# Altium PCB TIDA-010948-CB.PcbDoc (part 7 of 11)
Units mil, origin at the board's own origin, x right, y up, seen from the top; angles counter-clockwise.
Board outline 8100 x 8400 mil, 8 copper layers (L01 - TOP, L02 - GND, L03 - SIG, L04 - GND, L05 - PWR, L06 - SIG, L07 - GND, L08 - BOTTOM), stack 59.656 mil thick; 711 components, 572 nets, 2646 pads, 1325 vias.
Unrouted connection lines stored in the file: 988.
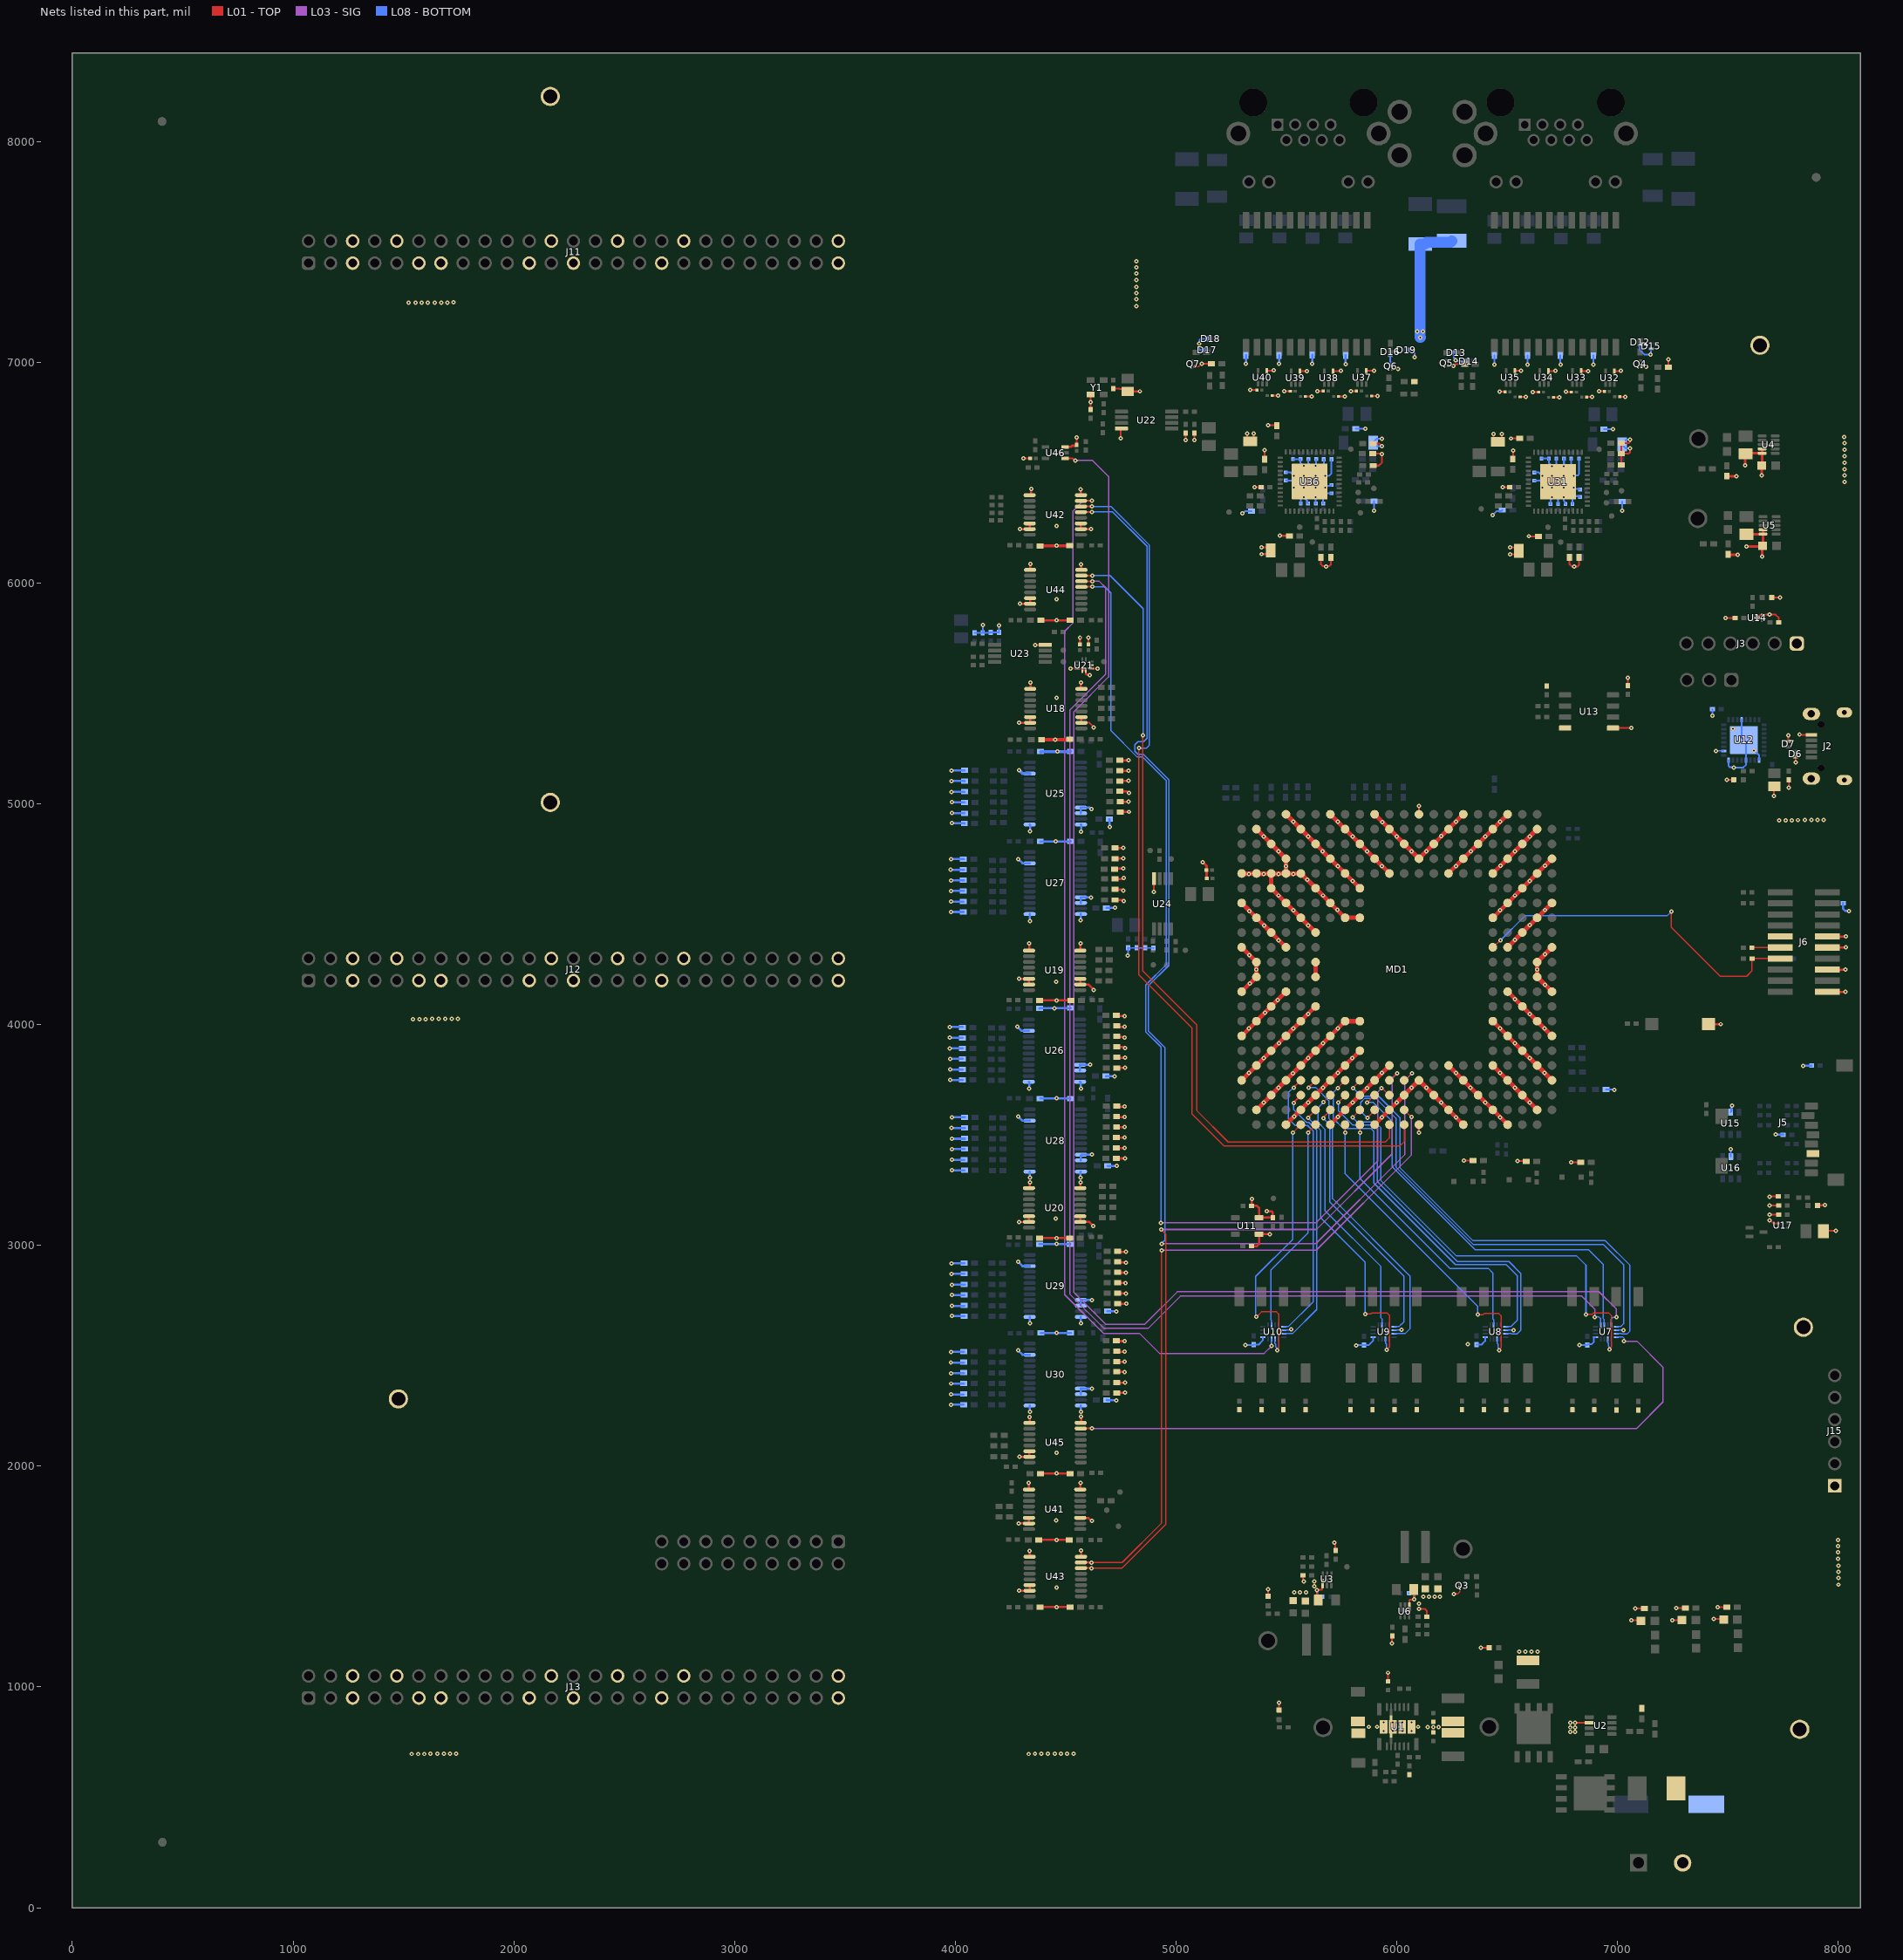
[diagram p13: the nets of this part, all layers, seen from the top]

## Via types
v1: diameter 19.68, hole 7.87, L01 - TOP to L08 - BOTTOM, 1310 vias
v2: diameter 20, hole 7.87, L01 - TOP to L08 - BOTTOM, tented both sides, 7 vias
v3: diameter 200, hole 144, L01 - TOP to L08 - BOTTOM, 6 vias
v4: diameter 20, hole 8, L01 - TOP to L08 - BOTTOM, tented both sides, 2 vias

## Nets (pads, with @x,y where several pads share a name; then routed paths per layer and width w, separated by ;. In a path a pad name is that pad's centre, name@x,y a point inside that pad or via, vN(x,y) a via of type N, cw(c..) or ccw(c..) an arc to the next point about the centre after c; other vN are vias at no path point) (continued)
GND: C1.1 C2.1 C3.2 C4.1 C5.1 C6.2 C7.2 C8.1 C10.1 C12.1 C13.2 C15.2 C17.2 C18.2 C19.2 C20.1 C21.2 C22.2 C24.2 C26.2 C27.2 C28.2 C29.2 C30.2 C31.2 C32.2 C33.2 C35.2 C41.1 C42.1 C43.1 C44.2 C45.2 C46.2 C47.1 C48.2 C49.1 C50.2 C51.1 C52.2 C53.2 C54.2 C55.2 C56.1 C57.2 C58.2 C59.2 C60.2 C61.2 C62.2 C63.2 C64.2 C65.2 C66.2 C67.2 C68.2 C69.2 C70.2 C71.2 C72.2 C73.2 C74.2 C75.2 C76.2 C77.2 C78.2 C79.1 C80.1 C81.2 C82.2 C83.2 C84.2 C85.2 C86.2 C87.2 C88.2 C89.2 C90.2 C91.2 C92.2 C93.1 C94.1 C95.2 C96.2 C97.2 C98.2 C99.2 C100.2 C101.1 C102.2 C103.2 C104.2 C105.2 C106.2 C107.2 C108.1 C109.2 C110.2 C111.2 C112.2 C113.2 C114.2 C115.2 C116.2 C117.2 C118.2 C119.2 C120.2 C121.2 C122.2 C123.2 C124.2 C125.2 C126.2 C127.2 C128.2 C129.2 C130.2 C131.2 C132.2 C133.2 C134.2 C135.2 C136.1 C137.2 C138.2 C139.1 C140.2 C142.1 C143.1 C144.1 C145.1 C146.1 C147.1 C148.1 C149.1 C150.2 C151.2 C152.2 C153.2 C154.2 C155.2 C156.2 C157.2 C158.2 C159.2 C160.2 C161.2 C162.2 C163.2 C164.2 C165.2 C166.2 C167.2 C168.2 C169.2 C170.2 C171.2 C172.2 C173.2 C174.2 C175.2 C176.2 C177.1 C178.1 C179.2 C180.2 C181.1 C182.2 C184.1 C185.1 C186.1 C187.1 C188.1 C189.1 C190.1 C191.1 C193.1 C194.2 C195.1 C196.2 C197.1 C198.2 C199.1 C200.2 C201.1 C202.2 C203.2 C204.2 C205.1 C206.1 D1.1 D2.1 D3.1 D4.1 D11.1 D12.1 D13.1 D14.1 D15.1 D16.1 D17.1 D18.1 D19.1 J1.2 J5.6 J6.10 J6.12 J6.16 J6.20 J11.5 J11.6 J11.10 J11.11 J11.13 J11.21 J11.24 J11.25 J11.30 J11.33 J11.36 J11.49 J11.50 J12.5 J12.6 J12.10 J12.11 J12.13 J12.21 J12.24 J12.25 J12.30 J12.33 J12.36 J12.49 J12.50 J13.5 J13.6 J13.10 J13.11 J13.13 J13.21 J13.24 J13.25 J13.30 J13.33 J13.36 J13.49 J13.50 J15.1 MD1.A4 MD1.A7 MD1.A10 MD1.A13 MD1.A16 MD1.A19 MD1.AA2 MD1.AA5 MD1.AA8 MD1.AA11 MD1.AA15 MD1.AA18 MD1.AA21 MD1.AB4 MD1.AB7 MD1.AB10 MD1.AB13 MD1.AB16 MD1.AB19 MD1.B2 MD1.B5 MD1.B8 MD1.B11 MD1.B15 MD1.B18 MD1.B21 MD1.C3 MD1.C6 MD1.C9 MD1.C12 MD1.C14 MD1.C17 MD1.C20 MD1.D4 MD1.D7 MD1.D10 MD1.D13 MD1.D16 MD1.D19 MD1.D22 MD1.E1 MD1.E2 MD1.E3 MD1.E4 MD1.E5 MD1.E8 MD1.E11 MD1.E15 MD1.E18 MD1.E21 MD1.F3 MD1.F6 MD1.F9 MD1.F20 MD1.G1 MD1.G4 MD1.G7 MD1.G19 MD1.G22 MD1.H2 MD1.H5 MD1.H8 MD1.H9 MD1.H18 MD1.H21 MD1.J3 MD1.J6 MD1.J20 MD1.K1 MD1.K4 MD1.K19 MD1.K22 MD1.L2 MD1.L6 MD1.L21 MD1.M2 MD1.M6 MD1.M21 MD1.N1 MD1.N4 MD1.N19 MD1.N22 MD1.P3 MD1.P6 MD1.P20 MD1.R2 MD1.R5 MD1.R8 MD1.R9 MD1.R18 MD1.R21 MD1.T1 MD1.T4 MD1.T7 MD1.T19 MD1.T22 MD1.U3 MD1.U6 MD1.U9 MD1.U20 MD1.V2 MD1.V5 MD1.V8 MD1.V11 MD1.V15 MD1.V18 MD1.V21 MD1.W1 MD1.W4 MD1.W7 MD1.W10 MD1.W13 MD1.W16 MD1.W19 MD1.W22 MD1.Y3 MD1.Y6 MD1.Y9 MD1.Y12 MD1.Y14 MD1.Y17 MD1.Y20 NT1.2 NT2.2 Q3.2 Q4.2 Q5.2 Q6.2 Q7.2 R4.2 R12.1 R17.1 R18.1 R19.1 R23.1 R25.1 R26.1 R35.1 R36.1 R37.1 R38.1 R39.1 R40.1 R41.1 R42.1 R51.1 R52.1 R53.1 R54.1 R55.1 R56.1 R57.1 R58.1 R60.1 R83.1 R84.1 R89.1 R90.1 R109.2 R131.2 R132.2 R145.2 R146.2 R147.2 R148.2 R149.2 R150.2 R151.2 R152.2 R153.2 R154.2 R155.2 R156.2 R159.2 R160.2 R173.2 R174.2 R175.2 R176.2 R177.2 R178.2 R179.2 R180.2 R181.2 R182.2 R183.2 R184.2 R186.2 R193.2 R194.2 R195.2 R196.2 R197.2 R198.2 R200.2 R207.2 R208.2 R209.2 R210.2 R211.2 R212.2 R221.1 R222.1 R223.1 R224.1 R225.1 R226.1 R227.1 R235.2 R252.1 R261.1 R262.1 R263.1 R264.1 R265.1 R266.1 R267.1 R275.2 R314.1 R315.1 R316.1 S1.1 TP1.1 TP2.1 TP3.1 TP4.1 TP40.1 TP41.1 U1.17 U1.18 U1.19 U1.20 U2.2 U3.4@5664.31,1468.28 U4.9 U4.10 U5.9 U5.10 U6.4@6056.69,1361.72 U7.6 U7.13 U8.6 U8.13 U9.6 U9.13 U10.6 U10.13 U11.1 U11.3 U13.4 U15.2 U16.2 U17.C1 U18.2 U18.3 U18.8 U18.9 U18.14 U18.15 U19.2 U19.3 U19.8 U19.9 U19.14 U19.15 U20.2 U20.3 U20.8 U20.9 U20.14 U20.15 U21.1 U21.2 U21.3 U21.4 U21.10 U22.4 U23.4 U24.4 U25.9 U25.10 U25.12 U25.13 U25.22 U26.9 U26.10 U26.12 U26.13 U26.22 U27.9 U27.10 U27.12 U27.13 U27.22 U28.9 U28.10 U28.12 U28.13 U28.22 U29.9 U29.10 U29.12 U29.13 U29.22 U30.9 U30.10 U30.12 U30.13 U30.22 U31.49 U32.4 U33.4 U34.4 U35.4 U36.49 U37.4 U38.4 U39.4 U40.4 U41.3 U41.8 U41.9 U41.14 U41.15 U42.2 U42.3 U42.8 U42.9 U42.14 U42.15 U43.8 U43.9 U43.14 U43.15 U44.8 U44.9 U44.14 U44.15 U45.8 U45.9 U45.14 U45.15 U46.3 Y1.2 | length 27395.5
  L01 - TOP w6: v1(4521.5,5613) 4521.81,5612.69 4550.84,5612.69 U21.10@4551.15,5612.39 U21.10@4551.21,5612.32 ; Q7.2@5084.89,6980.2 5100.7,6980.2 5103.15,6980.2 5115.44,6992.5 v1(5117.5,6992.5) ; Q6.2@5979.39,6969.7 6004.8,6969.7 v1(6005.5,6969) ; Q5.2@6232.39,6983.7 v1@6260.2,6983.7 ; v1(6259,1421) 6276,1421 6284.2,1429.2 Q3.2@6284.2,1452.95 ; Q4.2@7109.54,6979.85 v1@7130.35,6979.85
  L01 - TOP w8: v1(4289,3106.5) 4289.24,3106.26 4333.62,3106.26 U20.15@4333.86,3106.02 ; v1(4308,6564.5) C203.2@4338.51,6564.5 ; v1(4361.5,5719.5) 4361.69,5719.69 4406.98,5719.69 U23.4@4407.17,5719.89 ; v1@4457.66,6168.5 v1(4459.16,6170) ; v1(4549,6658.5) 4549.25,6658.25 4549.25,6626.24 C204.2@4549.5,6625.99 ; U21.10@4551.21,5612.32 4574.71,5612.32 4574.77,5612.26 U21.1@4574.77,5606.48 U21.1@4574.83,5606.42 ; C55.2@4564.5,5721.99 v1(4564.5,5752.5) ; U18.2@4571.44,5367.02 4607.81,5367.02 4627.5,5347.33 v1(4627.5,5345) ; U21.1@4574.83,5605.5 4590.45,5605.5 4590.52,5605.43 U21.2@4590.52,5604.51 4590.58,5604.45 4590.58,5588.19 4593.03,5585.74 4607.26,5585.74 v1(4609.5,5583.5) ; C56.1@4603,5721.99 v1(4603,5752) ; R109.2@4612,6786.19 4612.25,6786.44 4612.25,6818.25 v1(4612.5,6818.5) 4612.5,6853.55 Y1.2@4612.97,6854.02 Y1.2@4612.57,6854.42 ; U21.4@4614.14,5628.13 U21.3@4614.14,5612.39 4614.2,5612.32 4644.18,5612.32 v1(4645,5611.5) ; C57.2@4715.5,6879.81 4744.15,6879.81 4745.18,6878.78 4769.11,6878.78 C58.2@4780.05,6867.85 ; v1(4749.5,6655.5) 4749.5,6696.79 U22.4@4752.33,6699.61 ; C58.2@4780.08,6867.87 v1(4836.55,6867.87) ; v1(4899.5,4601.5) 4899.56,4601.56 4899.56,4661.12 U24.4@4899.61,4661.17 ; C54.2@5043,6679.31 5043.25,6679.06 5043.25,6648.75 v1(5043.5,6648.5) ; v1(5082.5,6648) 5082.75,6648.25 5082.75,6678.56 C53.2@5083,6678.81 ; v1@5114.34,6992.5 v1(5117.5,6992.5) 5118.25,6993.25 5159.13,6993.25 C178.1@5159.88,6994 ; v1(5321.5,6677) 5321.5,6653.43 5336,6638.93 5352.5,6655.43 v1(5352.5,6677.5) ; v1(5336.5,6874) 5337,6874.5 5366.98,6874.5 C191.1@5367.48,6875 ; v1(5355.5,6434) 5355.75,6433.75 5385.56,6433.75 C180.2@5385.81,6433.5 ; v1(5387.5,6131) 5412.07,6131 C158.2@5428.07,6147 5412.57,6162.5 v1(5387.5,6162.5) ; C163.2@5400.75,6555.87 5401,6556.12 v1(5401,6603) ; U40.4@5410.69,6961.13 5411.62,6962.07 5442.07,6962.07 v1(5443,6963) ; v1(5416,6715) 5455.62,6715 R275.2@5457,6713.62 ; D4.1@5417,1410.65 v1(5417,1443) ; C190.1@5434.02,6849 5434.27,6849.25 5461.75,6849.25 v1(5462,6849.5) ; D2.1@5466.69,895.65 5466.84,895.81 5466.84,927.84 v1(5467,928) ; v1(5470.5,6214.5) 5471,6214 5512.38,6214 C165.2@5512.88,6213.5 ; v1(5490,6868.5) 5490.25,6868.75 5517.23,6868.75 C189.1@5517.48,6869 ; U39.4@5559.69,6959.13 5560.12,6959.57 5591.57,6959.57 v1(5592,6960) ; R17.1@5575.31,1506 5575.31,1486.9 ccw(c5587.9,1486.9) v1(5579,1478) ; C188.1@5585.52,6845 v1(5613.5,6845) ; v1(5640,6869.5) C187.1@5667.48,6869.5 ; C13.2@5644.63,1393 5639,1398.63 v1(5639,1438) 5641.24,1440.24 5659.96,1440.24 5662.41,1442.69 5662.41,1466.38 U3.4@5664.31,1468.28 ; R261.1@5656.5,6115.38 5656.5,6085 5665,6076.5 5677.5,6076.5 v1(5679,6075) 5681.24,6077.24 5694.24,6077.24 5700.5,6083.5 R262.1@5700.5,6115.88 ; U38.4@5711.69,6959.13 5712.62,6960.07 5745.07,6960.07 v1(5746,6961) ; v1(5718,1653) 5720.24,1650.76 5720.24,1620.45 R19.1@5723,1617.68 ; C186.1@5736.02,6845.5 v1(5764,6845.5) ; v1(5792,6869.5) 5792.25,6869.75 5817.23,6869.75 C185.1@5817.48,6870 ; U37.4@5861.69,6960.13 5862.62,6961.07 5895.07,6961.07 v1(5896,6962) ; C184.1@5886.02,6846.5 v1(5912,6846.5) ; R265.1@5891.62,6585.5 5932,6585.5 v1(5933,6584.5) 5933,6546.5 5918.5,6532 R266.1@5892.12,6532 ; R264.1@5892.12,6632.5 5919.87,6632.5 5932.5,6619.87 v1(5932.5,6619.5) ; C8.1@5961,1031.68 v1(5961,1064) ; NT2.2@5974,856 5974,847.39 v1(5982.29,839.1) ; v1(5978,1197) 5978.5,1197.5 5978.5,1229.82 R26.1@5979,1230.32 ; v1(5982.29,799.73) U1.19@5974,791.44 ; v1@6005.15,6969.35 v1(6005.5,6969) ; U6.4@6056.69,1361.72 6056.69,1391.68 6060,1395 6076,1395 v1(6078,1397) 6078,1439.37 C21.2@6076.37,1441 ; MD1.A13@6100.39,4952.36 MD1.A13@6100.39,4952.36 6100.45,4989.95 v1(6100.5,4990) ; v1(6101,1354) 6127,1354 6135.69,1345.32 R25.1@6135.69,1318 ; v1@6260.2,6983.7 6267.75,6991.25 6307.13,6991.25 C136.1@6307.38,6991.5 ; v1(6303.5,3385) C43.1@6344.88,3385 ; v1(6381,1177) D1.1@6418.35,1177 ; v1(6435,6308) v1@6435.75,6308.75 ; v1(6439,6675) 6439,6657.58 6456.65,6639.93 C109.2@6457.5,6639.93 6458.35,6639.93 6476,6657.58 v1(6476,6675.5) ; v1(6465,6866) C149.1@6489.98,6866 ; v1(6480.36,6433.53) C138.2@6510.81,6433.5 ; v1(6512.36,6130.53) 6537.1,6130.53 C116.2@6552.57,6146 6536.54,6162.03 v1(6512.36,6162.03) ; v1(6517.5,6654.5) 6517.75,6654.75 6556.13,6654.75 R235.2@6556.38,6655 ; C121.2@6525.5,6561.62 6526.25,6562.37 6526.25,6598.75 v1(6527,6599.5) ; U35.4@6534.19,6959.63 6535.37,6960.82 6561.82,6960.82 v1(6563,6962) ; v1(6547.5,3382) 6548,3381.5 6585.88,3381.5 C42.1@6586.38,3381 ; C148.1@6558.52,6843 v1(6584,6843) ; v1(6598.5,6212) 6598.75,6211.75 6642.13,6211.75 C123.2@6642.38,6211.5 ; v1(6616.5,6865) C147.1@6641.98,6865 ; U34.4@6686.19,6959.63 6687.12,6960.57 6717.07,6960.57 v1(6718,6961.5) ; C146.1@6710.52,6841.5 6710.77,6841.75 6735.75,6841.75 v1(6736,6842) ; v1(6766.5,6866) 6766.75,6865.75 6791.23,6865.75 C145.1@6791.48,6865.5 ; R221.1@6782,6115.88 6782,6086.5 6793,6075.5 6802.89,6075.5 v1(6803.86,6074.53) ; v1(6789.5,3376) 6790,3376.5 6832.88,3376.5 C41.1@6833.38,3377 ; v1(6803.86,6074.53) 6819,6074.5 6825,6080.5 R222.1@6825,6115.88 ; v1(6807,837) 6807.4,837.4 6871.42,837.4 U2.2@6871.82,837.8 ; U33.4@6835.19,6959.63 6835.62,6960.07 6867.07,6960.07 v1(6867.5,6960.5) ; C144.1@6860.02,6842 6860.27,6842.25 6885.25,6842.25 v1(6885.5,6842.5) ; v1(6916,6868.5) 6916.25,6868.25 6940.73,6868.25 C143.1@6940.98,6868 ; U32.4@6985.19,6959.13 6986.37,6960.32 7014.32,6960.32 v1(7015.5,6961.5) ; C142.1@7009.52,6844 v1(7034.5,6844) ; R225.1@7016.12,6585.5 R225.1@7016.62,6585.5 ; R224.1@7016.87,6633.25 R224.1@7016.62,6633.5 ; R226.1@7017.62,6530.5 7016.62,6531.5 R225.1@7016.62,6585.5 ; v1(7056.65,6610.12) 7056.65,6592.15 7050,6585.5 R225.1@7016.62,6585.5 ; v1(7057.29,6649.09) 7057.19,6649 7057.19,6640.13 7050.56,6633.5 R224.1@7016.62,6633.5 ; v1(7062,1301.5) 7104.76,1301.5 R314.1@7106.36,1299.9 ; v1(7080,1356) 7080.3,1355.7 7120.94,1355.7 C177.1@7121.24,1355.4 ; v1@7130.35,6979.85 v1(7130.5,6980) ; C139.1@7230.62,6977.5 7231,6977.88 v1(7231,7014) ; v1(7248,1302.5) R315.1@7291,1302.5 ; v1(7265,1356.5) 7265.25,1356.75 7306.63,1356.75 C205.1@7306.88,1357 ; S1.1@7411.95,4002 7412.45,4001.5 v1(7466.5,4001.5) ; v1(7436,1307) 7477.93,1307 R316.1@7480.38,1304.55 ; v1(7453.5,1362) C206.1@7494.73,1362.02 ; v1(7688.5,3220) 7691.66,3220 7694.16,3222.5 R90.1@7728.82,3222.5 ; v1(7689,3113) 7692.16,3113 7705.32,3099.84 U17.C1@7729.32,3099.84 ; v1(7689,3140) C44.2@7729.31,3140 ; v1(7689,3181) R89.1@7729.32,3181 ; C46.2@7933,3064 7936,3067 v1(7989,3067) ; v1@7938.5,3182.5 v1(7939,3182) ; U1.19@5974,791.44 NT1.2@5974,785 U1.19@5974,791.44 ; R225.1@7016.62,6585.5 R224.1@7016.62,6633.5
  L01 - TOP w10: v1(4287.5,1741) 4287.74,1740.76 4333.62,1740.76 U41.15@4333.86,1740.52 U41.14@4333.86,1766.11 ; v1(4288.5,5367) 4338.85,5367.01 U18.14@4338.86,5392.61 ; v1(4289,1436) 4336.85,1436.01 U43.14@4336.86,1461.61 ; v1(4289.5,4207) 4289.56,4207.06 4333.8,4207.06 U19.14@4333.86,4207.11 U19.15@4333.86,4181.52 ; v1(4291,2042) 4291.26,2042.26 4335.6,2042.26 U45.15@4335.86,2042.52 U45.14@4335.86,2068.11 ; v1(4292,6244.5) 4336.85,6244.51 U42.14@4336.86,6270.11 ; v1(4292.5,5906) 4338.85,5906.01 U44.14@4338.86,5931.61 ; v1(4333,1924) 4333,1894.92 U41.9@4333.86,1894.06 ; U20.15@4333.86,3106.02 U20.14@4333.86,3131.61 ; U20.9@4333.86,3259.57 U20.9@4333.86,3259.57 4337.5,3263.13 v1(4337.5,3284.5) ; U19.9@4333.86,4335.07 4334.5,4335.71 v1(4334.5,4368) ; U45.9@4335.86,2196.07 4337,2197.21 v1(4337,2223.5) ; U43.9@4336.86,1589.57 4337,1589.71 v1(4337,1617) ; U42.9@4336.86,6398.07 4340.42,6401.63 4343.52,6401.63 v1(4343.52,6425.5) ; U18.9@4338.86,5520.57 4341,5522.71 v1(4341,5550) ; U44.9@4338.86,6059.57 4339.5,6060.21 v1(4339.5,6087.5) ; C194.2@4378.06,1665.64 C194.2@4378.06,1665.64 4516.81,1665.57 C193.1@4516.88,1665.5 ; C50.2@4381.12,4109 4381.45,4109.32 4523.16,4109.32 C49.1@4523.48,4109.65 ; C52.2@4382.12,3032.5 4382.37,3032.75 4517.58,3032.75 C51.1@4517.83,3033 ; C198.2@4383.43,1361.62 4383.62,1361.81 4519.69,1361.81 C197.1@4519.88,1362 ; C202.2@4386.42,1966.16 4387.09,1966.83 4458.49,1966.83 v1(4459.16,1967.5) ; C200.2@4388.41,5831.71 4388.52,5831.61 4520.77,5831.61 C199.1@4520.88,5831.5 ; v1@4459.16,1966.58 4459.24,1966.5 4518.88,1966.5 C201.1@4519.38,1966 ; U46.3@4497.29,6615.59 4499.2,6617.5 4524.5,6617.5 4528.94,6621.94 4546.23,6621.94 4549.5,6625.2 C204.2@4549.5,6625.99 ; U41.3@4566.14,1766.11 4567.62,1764.63 4603.75,1764.63 4615.88,1752.5 v1(4618.5,1752.5) ; U41.8@4566.14,1894.06 4566.5,1894.42 v1(4566.5,1924) ; U20.3@4566.14,3131.61 U20.2@4566.14,3106.02 4606.98,3106.02 v1(4624.5,3088.5) ; U20.8@4566.14,3259.57 4567,3260.43 v1(4567,3285.5) ; U19.3@4566.14,4207.11 U19.2@4566.14,4181.52 4603.48,4181.52 4626.5,4158.5 v1(4626.5,4156) ; U19.8@4566.14,4335.07 4567,4335.93 v1(4567,4367.5) ; v1(4568,6425) 4568,6399.21 U42.8@4569.14,6398.07 ; U45.8@4568.14,2196.07 4569.5,2197.43 v1(4569.5,2224) ; v1(4568.5,5549) 4568.5,5523.21 U18.8@4571.14,5520.57 ; U43.8@4569.14,1589.57 4570,1590.43 v1(4570,1618.5) ; U42.3@4569.14,6270.11 U42.2@4569.14,6244.52 4569.4,6244.26 4613.74,6244.26 v1(4614,6244) ; v1(4570,6085.5) 4570,6060.71 U44.8@4571.14,6059.57 ; U18.2@4571.14,5367.02 U18.3@4571.14,5392.61 ; R174.2@4720.78,4752.34 4759.97,4752.34 v1(4760.13,4752.19) ; R176.2@4721.22,4659.59 4755.47,4659.59 4760.88,4665 v1(4763.5,4665) ; R173.2@4721.22,4800.09 4760.03,4800.09 v1(4760.13,4800.19) ; R175.2@4721.47,4706.34 4759.28,4706.34 v1(4760.13,4707.19) ; R177.2@4722.22,4612.09 4753.78,4612.09 4758.88,4607 v1(4761.5,4607) ; R178.2@4723.47,4565.34 4755.03,4565.34 4760.88,4559.5 v1(4763.5,4559.5) ; R180.2@4727.43,3581 4766.63,3581 v1(4766.78,3580.84) ; R182.2@4727.87,3488.25 4766.19,3488.25 v1(4766.28,3488.34) ; R179.2@4727.87,3628.75 4766.69,3628.75 v1(4766.78,3628.84) ; R152.2@4727.93,3990.5 4767.13,3990.5 v1(4767.28,3990.34) ; R181.2@4728.12,3535 4765.94,3535 v1(4766.78,3535.84) ; R208.2@4728.16,2518.56 4767.35,2518.56 v1(4767.51,2518.4) ; R151.2@4728.37,4038.25 4767.19,4038.25 v1(4767.28,4038.34) ; R210.2@4728.6,2425.81 4729.44,2426.65 4766.52,2426.65 v1(4767.01,2426.16) ; R207.2@4728.6,2566.31 4767.41,2566.31 v1(4767.51,2566.4) ; R153.2@4728.62,3944.5 4729.11,3944.01 4765.43,3944.01 v1(4767.28,3942.16) ; R209.2@4728.85,2472.56 4766.66,2472.56 v1(4767.51,2473.4) ; R183.2@4728.87,3440.75 4767.69,3440.75 v1(4767.78,3440.84) ; R154.2@4728.86,3898.24 4762.14,3898.24 4767.35,3893.03 v1(4769,3893.03) ; R155.2@4729.37,3850.25 4768.19,3850.25 v1(4768.28,3850.34) ; R211.2@4729.6,2378.31 4768.41,2378.31 v1(4768.51,2378.4) ; R184.2@4730.12,3394 4767.94,3394 v1(4768.78,3394.84) ; R156.2@4730.62,3803.5 4768.44,3803.5 v1(4769.28,3804.34) ; R212.2@4730.85,2331.56 4768.66,2331.56 v1(4769.51,2332.4) ; R194.2@4732.93,2922.5 4772.13,2922.5 v1(4772.28,2922.34) ; R196.2@4733.37,2829.75 4771.69,2829.75 v1(4771.78,2829.84) ; R193.2@4733.37,2970.25 4772.19,2970.25 v1(4772.28,2970.34) ; R195.2@4733.62,2876.5 4771.44,2876.5 v1(4772.28,2877.34) ; R197.2@4734.37,2782.25 4773.19,2782.25 v1(4773.28,2782.34) ; R198.2@4735.62,2735.5 4773.44,2735.5 v1(4774.28,2736.34) ; R147.2@4745,5102.81 4745.75,5103.56 4783.75,5103.56 v1(4784.5,5104.31) ; R146.2@4745,5149.81 4745.15,5149.66 4784.34,5149.66 v1(4784.5,5149.5) ; R148.2@4745.5,5056.81 4746.29,5056.01 4775.87,5056.01 4783.38,5048.5 v1(4786,5048.5) ; R145.2@4745.5,5197.31 4745.59,5197.41 4784.41,5197.41 v1(4784.5,5197.5) ; R149.2@4746.5,5009.31 4746.59,5009.41 4785.41,5009.41 v1(4785.5,5009.5) ; R150.2@4747,4961.81 4747.84,4962.66 4785.66,4962.66 v1(4786.5,4963.5) ; C28.2@5341.69,2996 5366,2996 5376.13,3006.13 U11.1@5376.13,3050.6 5376.33,3050.8 5423.8,3050.8 v1(5424,3051) ; v1(5343,3211) 5342.84,3210.84 5342.84,3179.16 R60.1@5342.69,3179 5366,3179 5377,3168 5377,3126.27 U11.3@5376.28,3125.54 ; U11.3@5376.13,3125.4 U11.3@5376.28,3125.54 ; v1(5411,3155) 5412.85,3153.15 5434,3153.15 5438,3149.14 C29.2@5438,3125.69 5437.86,3125.54 U11.3@5376.28,3125.54 ; v1(6100,3510) 6100.2,3510.2 6100.2,3546.65 MD1.AB13@6100.39,3546.84 ; D11.1@7906.13,3180.4 7906.93,3181.2 7938.2,3181.2 v1(7939,3182) ; J6.20@7950.5,4149 7951,4148.5 8032.5,4148.5 v1(8033,4148) ; J6.16@7950.5,4249 v1(8032,4249) ; J6.12@7950.5,4349 7951,4349.5 8034.5,4349.5 v1(8035,4350) ; J6.10@7950.5,4399 v1(8035,4399)
  L01 - TOP w12: C196.2@4383.62,6167 4385.12,6168.5 4457.66,6168.5 4516.88,6168.5 C195.1@4518.38,6170 ; v1(5121.5,4735.5) 5137.51,4719.49 C174.2@5137.51,4700 5138.24,4699.27 5138.24,4663.27 C168.2@5138.97,4662.54 ; R18.1@7495.6,6484.64 7495.79,6484.45 7537.41,6484.45 v1(7537.6,6484.26) ; R23.1@7501.61,6129.43 7502.3,6128.74 7542.92,6128.74 v1(7543.61,6128.05) ; v1(7578.6,6533.26) 7578.6,6583.26 C19.2@7580.6,6585.26 7583.6,6588.26 7653.44,6588.26 7654.44,6587.26 U4.10@7655.07,6587.89 ; v1(7583.61,6165.05) 7653.11,6165.05 C22.2@7655.61,6167.54 ; C24.2@7584.61,6221.05 7585.24,6221.68 U5.10@7659.08,6221.68 ; C15.2@7653.1,6532.26 C15.2@7653.6,6532.76 ; v1(7653.6,6488.26) C15.2@7653.6,6532.76 ; U4.9@7655.07,6607.58 7654.18,6606.69 7655.07,6606.69 U4.10@7655.07,6587.89 ; v1(7655.61,6121.05) C22.2@7655.61,6167.54 ; U5.9@7659.08,6241.36 U5.10@7659.08,6221.68 ; C15.2@7653.6,6532.76 7655.07,6534.23 U4.10@7655.07,6587.89 ; C22.2@7655.61,6167.54 C22.2@7657.11,6169.05 7659.08,6171.02 U5.10@7659.08,6221.68
  L01 - TOP w15: C48.2@4390.62,5290 4391.37,5290.75 4518.13,5290.75 C47.1@4518.88,5291.5
  L01 - TOP w20: MD1.W1@5297.24,3747.63 MD1.V2@5364.17,3814.56 MD1.U3@5431.1,3881.49 v1(5465.61,3916) MD1.T4@5498.03,3948.42 v1(5531.94,3982.27) v1(5531.94,3982.27) ; MD1.T1@5297.24,3948.42 v1(5330.75,3981.92) 5402.33,4053.5 v1(5402.5,4053.5) 5402.5,4053.67 MD1.P3@5431.1,4082.28 5459.83,4111 v1(5460.5,4111) 5460.5,4111.67 MD1.N4@5498.03,4149.21 ; MD1.N1@5297.24,4149.26 MD1.M2@5364.1,4216.11 ; MD1.K1@5297.24,4349.99 MD1.L2@5364.17,4283.06 v1(5364.17,4249.6) MD1.M2@5364.17,4216.14 ; MD1.G1@5297.24,4550.78 5332.32,4515.71 v1(5332.32,4514.32) ; MD1.E1@5297.24,4684.64 5298.95,4682.93 v1(5330.71,4682.93) ; v1@5330.71,4684.64 MD1.E2@5364.17,4684.64 5365.88,4682.93 v1(5397.64,4682.93) ; v1@5333.01,4515.01 MD1.H2@5364.17,4483.85 5398.32,4449.7 v1(5398.32,4448.32) ; MD1.AA2@5364.17,3613.77 v1(5397.64,3647.24) MD1.Y3@5431.1,3680.7 v1(5464.57,3714.17) MD1.W4@5498.03,3747.63 5529.9,3779.5 v1(5530,3779.5) ; MD1.B2@5364.17,4885.43 5396.74,4852.86 v1(5396.74,4851.06) ; v1@5397.64,4684.64 MD1.E3@5431.1,4684.64 ; v1@5397.64,4851.96 MD1.C3@5431.1,4818.5 MD1.D4@5498.03,4751.57 v1(5498.03,4718.1) MD1.E4@5498.03,4684.64 ; v1@5399.01,4449.01 MD1.J3@5431.1,4416.92 5464.83,4383.19 v1(5464.83,4381.81) ; v1(5464.57,4682.93) 5432.81,4682.93 MD1.E3@5431.1,4684.64 ; v1@5464.57,4684.64 MD1.E4@5498.03,4684.64 ; v1@5465.53,4382.5 MD1.K4@5498.03,4349.99 ; MD1.AB4@5498.03,3546.84 MD1.AA5@5564.96,3613.77 MD1.Y6@5631.89,3680.7 MD1.W7@5698.82,3747.63 MD1.V8@5765.75,3814.56 MD1.U9@5832.68,3881.49 ; MD1.A4@5498.03,4952.36 MD1.B5@5564.96,4885.43 v1(5598.43,4851.96) MD1.C6@5631.89,4818.5 v1@5664.69,4785.69 ; v1@5531.5,3781.1 MD1.V5@5564.96,3814.56 5598.16,3847.76 v1(5598.16,3847.86) ; v1(5531.5,4682.93) 5499.74,4682.93 MD1.E4@5498.03,4684.64 ; v1@5531.5,4684.64 5570.2,4684.64 5570.2,4680.3 5631.89,4618.61 MD1.F6@5631.89,4617.71 v1(5665.35,4584.25) MD1.G7@5698.82,4550.78 MD1.H8@5765.75,4483.85 MD1.H9@5832.68,4483.85 ; v1@5531.78,3982.17 MD1.R5@5564.96,4015.35 v1(5598,4048.39) MD1.P6@5631.89,4082.28 ; v1@5598.43,3848.03 MD1.U6@5631.89,3881.49 MD1.T7@5698.82,3948.42 MD1.R8@5765.75,4015.35 MD1.R9@5832.68,4015.35 ; MD1.M6@5631.89,4216.14 MD1.L6@5631.89,4283.06 ; MD1.J6@5631.89,4416.92 MD1.H5@5564.96,4483.85 MD1.G4@5498.03,4550.78 MD1.F3@5431.1,4617.71 MD1.E3@5431.1,4684.64 ; v1(5663.5,4784.5) 5696.43,4751.57 MD1.D7@5698.82,4751.57 MD1.E8@5765.75,4684.64 MD1.F9@5832.68,4617.71 ; MD1.AB7@5698.82,3546.84 MD1.AA8@5765.75,3613.77 MD1.Y9@5832.68,3680.7 MD1.W10@5899.61,3747.63 MD1.V11@5966.54,3814.56 ; MD1.A7@5698.82,4952.36 MD1.B8@5765.75,4885.43 MD1.C9@5832.68,4818.5 MD1.D10@5899.61,4751.57 MD1.E11@5966.54,4684.64 ; MD1.AB10@5899.61,3546.84 MD1.AA11@5966.54,3613.77 MD1.Y12@6033.46,3680.7 MD1.W13@6100.39,3747.63 MD1.Y14@6167.32,3680.7 MD1.AA15@6234.25,3613.77 MD1.AB16@6301.18,3546.84 ; MD1.A10@5899.61,4952.36 MD1.B11@5966.54,4885.43 MD1.C12@6033.46,4818.5 MD1.D13@6100.39,4751.57 v1(6133.5,4784.67) MD1.C14@6167.32,4818.5 v1@6201.91,4853.09 ; v1(6201.5,4853.5) 6202.32,4853.5 MD1.B15@6234.25,4885.43 v1(6267.72,4918.89) MD1.A16@6301.18,4952.36 ; MD1.V15@6234.25,3814.56 MD1.W16@6301.18,3747.63 MD1.Y17@6368.11,3680.7 MD1.AA18@6435.04,3613.77 MD1.AB19@6501.97,3546.84 ; MD1.E15@6234.25,4684.64 MD1.D16@6301.18,4751.57 MD1.C17@6368.11,4818.5 MD1.B18@6435.04,4885.43 MD1.A19@6501.97,4952.36 ; MD1.V18@6435.04,3814.56 MD1.W19@6501.97,3747.63 MD1.Y20@6568.9,3680.7 MD1.AA21@6635.83,3613.77 ; MD1.R18@6435.04,4015.35 MD1.T19@6501.97,3948.42 MD1.U20@6568.9,3881.49 MD1.V21@6635.83,3814.56 MD1.W22@6702.76,3747.63 ; MD1.H18@6435.04,4483.85 MD1.G19@6501.97,4550.78 MD1.F20@6568.9,4617.71 MD1.E21@6635.83,4684.64 MD1.D22@6702.76,4751.57 ; MD1.E18@6435.04,4684.64 MD1.D19@6501.97,4751.57 MD1.C20@6568.9,4818.5 MD1.B21@6635.83,4885.43 ; MD1.N19@6501.97,4149.21 MD1.P20@6568.9,4082.28 MD1.R21@6635.83,4015.35 MD1.T22@6702.76,3948.42 ; MD1.K19@6501.97,4349.99 MD1.J20@6568.9,4416.92 MD1.H21@6635.83,4483.85 MD1.G22@6702.76,4550.78 ; MD1.N22@6702.76,4149.21 MD1.M21@6635.83,4216.14 MD1.L21@6635.83,4283.06 MD1.K22@6702.76,4349.99
  L08 - BOTTOM w6: C64.2@4782.27,4347.66 C65.2@4821.26,4347.66 ; C65.2@4821.26,4347.66 4896.19,4347.72 C63.2@4897.08,4346.82 ; U10.6@5487.24,2615.87 5488.18,2616.81 5518.84,2616.81 v1(5521,2618.97) ; U9.6@5988.24,2615.87 5989.18,2616.81 6019.84,2616.81 v1(6021,2617.97) ; U8.6@6494.24,2615.87 6494.31,2615.94 v1@6528.94,2615.94 ; U7.6@6994.24,2615.87 6994.31,2615.94 v1@7026.94,2615.94
  L08 - BOTTOM w8: C60.2@4086.5,5775.19 4086.73,5774.96 4121.77,5774.96 4125,5778.19 4124.46,5778.72 4124.46,5809.46 v1(4125,5810) ; C61.2@4125,5774.94 4155.75,5774.94 C62.2@4156.25,5775.44 ; C62.2@4160.12,5776.19 C59.2@4198,5776.19 v1(4198,5808) ; v1(4781.5,4312.5) 4781.88,4312.88 C64.2@4781.88,4347.66 ; C63.2@4897.08,4346.82 C63.2@4897.22,4346.69 ; D17.1@5127.7,7055.5 5109.5,7055.5 5104.5,7060.5 v1(5104.5,7085) 5106.74,7087.24 5106.74,7101.24 5112.11,7106.61 D18.1@5143.63,7106.61 ; v1(5300,6315) 5303.16,6315 5314.16,6326 R267.1@5342.38,6326 ; v1(5315,2548) 5316.16,2549.16 5350.84,2549.16 C33.2@5352,2550.31 5373.31,2550.31 5392.76,2569.76 U10.13@5392.76,2584.38 ; C152.2@5497.49,6465 5497.99,6464.5 5525.5,6464.5 5532.04,6471.04 5532.04,6484.21 v1(5534.28,6486.44) 5533.61,6486.44 5518.55,6501.5 C166.2@5497.49,6501.5 ; C157.2@5529,6561.01 C170.2@5564,6561.01 5564,6544.51 v1(5578.17,6530.34) ; C167.2@5565.5,6359.99 5565.5,6383.31 5570.19,6388 5577.57,6388 v1(5578.17,6388.61) 5593.73,6373.05 5593.73,6364.26 C153.2@5598,6359.99 ; C173.2@5599.5,6561.01 5599.5,6542 5611.16,6530.34 v1(5632.11,6530.34) 5633.56,6531.78 5633.56,6559.56 C161.2@5635,6561.01 ; C159.2@5633,6359.99 5632.56,6360.44 v1@5632.56,6388.16 ; v1@5633.39,6387.33 v1@5632.56,6388.16 ; v1(5639,1438) 5640.84,1436.16 5640.84,1416.16 5648,1409 C12.1@5662.31,1409 ; C171.2@5666.5,6359.99 5666.5,6383.92 5661.81,6388.61 v1(5632.11,6388.61) v1@5632.56,6388.16 ; C169.2@5669,6560.51 5669,6496.61 5676.01,6489.6 v1(5676.01,6486.44) 5676.45,6486 5694,6486 5704,6496 C156.2@5704,6560.51 ; C160.2@5705.01,6407 5682.52,6407 5677.84,6411.69 5677.84,6430.67 v1(5676.01,6432.5) 5679.17,6432.5 5686.9,6440.23 5700.74,6440.23 C172.2@5705.01,6444.5 ; C164.2@5814.12,6699 v1(5857.5,6699) ; v1(5816,2547) 5816.66,2547.66 5851.34,2547.66 C32.2@5852,2548.31 5872.31,2548.31 5893.76,2569.76 U9.13@5893.76,2584.38 ; v1(5896.5,6328) 5896.5,6370 R263.1@5896.75,6370.25 ; v1(5932.5,6619.5) 5908.98,6619.5 C155.2@5892.88,6635.6 5892.88,6636.35 5910.54,6654 v1(5932.5,6654) ; D16.1@5970.5,7034.2 5970.5,6983.95 5985.45,6969 v1(6005.5,6969) ; C20.1@6055.69,1425 6072,1425 6078,1419 v1(6078,1397) ; D19.1@6057.8,7055 6075,7055 6081,7049 6081,7023.5 v1(6080.5,7023) ; D13.1@6256.2,7043 6259.09,7040.11 6259.09,7019.57 6266.5,7012.16 v1(6266.5,7009) 6269.66,7009 6273.66,7005 D14.1@6314.2,7005 ; C31.2@6362,2551.31 6363.31,2550 6383,2550 6399.76,2566.76 U8.13@6399.76,2584.38 ; v1(6435,6308) 6452.79,6325.79 6473.69,6325.81 R227.1@6478.38,6330.5 ; C133.2@6441.5,7030.88 6441.75,7030.63 6441.75,6990.25 v1(6442,6990) ; v1@6528.94,2615.94 v1(6529,2616) ; v1(6592,6989.5) C134.2@6592,7030.38 ; C124.2@6622.49,6463.5 6647.5,6463.5 6656.9,6472.9 6656.9,6483.73 v1(6659.13,6485.97) 6658.08,6485.97 6643.55,6500.5 C110.2@6622.49,6500.5 ; C128.2@6655.3,6563.76 6655.37,6563.69 6689.54,6563.69 C115.2@6689.61,6563.63 6689.61,6543.29 v1(6703.03,6529.87) ; C125.2@6696,6357.99 6697.11,6359.1 6697.11,6379.05 6703.03,6384.97 v1(6703.03,6388.13) 6725.31,6388.13 6730,6383.45 C111.2@6730,6357.99 ; C118.2@6722.5,6564.01 6722.5,6542.5 6735.13,6529.87 v1(6756.97,6529.87) 6757.23,6530.13 6757.23,6563.74 C130.2@6757.5,6564.01 ; C137.2@6741,7031.38 6741.25,7031.13 6741.25,6989.75 v1(6741.5,6989.5) ; v1@6756.97,6385.08 v1(6756.97,6388.13) ; C117.2@6764,6357.99 6759.73,6362.26 6759.73,6369.77 6756,6373.5 6756,6387.17 v1(6756.97,6388.13) ; C114.2@6790,6563.53 6790,6499.99 6800.87,6489.13 v1(6800.87,6485.97) 6802.4,6487.5 6819.5,6487.5 6824.76,6492.76 C127.2@6824.76,6563.63 ; C129.2@6796,6357.99 6796,6382.5 6790.37,6388.13 v1(6756.97,6388.13) ; v1(6828,2548) 6828.16,2548.16 6861.84,2548.16 C30.2@6862,2548.31 6865.69,2552 6881,2552 6893,2564 6893,2584.31 6893.06,2584.38 U7.13@6899.76,2584.38 ; C119.2@6830.01,6389.5 6825.74,6393.77 6810.23,6393.77 6800.87,6403.13 v1(6800.87,6432.03) 6804.03,6432.03 6808.95,6427.11 6826.4,6427.11 C131.2@6830.01,6423.5 ; v1(6891,6989) 6891.25,6989.25 6891.25,7029.63 C140.2@6891.5,7029.88 ; C122.2@6938.41,6696.09 6938.66,6696.34 6979.04,6696.34 v1(6979.29,6696.59) ; C135.2@6947.12,3706.5 6947.87,3705.75 6984.75,3705.75 v1(6985.5,3705) ; v1(7021,6328) 7021,6368.53 R223.1@7021.74,6369.26 ; v1@7026.94,2615.94 v1(7027,2616) ; v1(7056.65,6610.12) 7038.47,6610.12 7020.82,6627.77 C113.2@7020.82,6628.35 7020.82,6631.44 7038.47,6649.09 v1(7057.29,6649.09) ; D12.1@7102.5,7077.7 7102.5,7054 7122.5,7034 v1(7149.5,7034) 7151.25,7035.75 7151.25,7059.16 D15.1@7153,7060.91 ; U15.2@7512,3603.2 7515.76,3606.96 7515.76,3630.76 v1(7518,3633) ; U16.2@7513,3402.2 v1(7513,3435)
  L08 - BOTTOM w10: v1(3974.57,3941.15) 3974.91,3940.81 C77.2@4033.09,3940.81 ; v1(3975.07,3988.65) 3975.23,3988.81 C78.2@4033.28,3988.81 ; v1(3975.57,3891.65) 3975.82,3891.9 C76.2@4033.7,3891.9 ; v1(3976.07,3750.15) 3976.72,3749.5 C73.2@4032.38,3749.5 ; v1(3976.07,3796.15) 3976.78,3795.44 C74.2@4032.63,3795.44 ; v1(3976.07,3845.15) 3976.66,3844.57 C75.2@4032.9,3844.57 ; v1(3979.67,4701.83) 3980.02,4701.48 C85.2@4038.2,4701.48 ; v1(3979.73,2469.72) 3980.07,2469.38 C106.2@4038.25,2469.38 ; v1(3980.17,4749.33) 3980.33,4749.48 C86.2@4038.38,4749.48 ; v1(3980.23,2517.22) 3980.38,2517.38 C107.2@4038.44,2517.38 ; v1(3980.67,4652.33) 3980.92,4652.58 C84.2@4038.8,4652.58 ; v1(3980.73,2420.22) 3980.98,2420.47 C105.2@4038.85,2420.47 ; v1(3981.17,4510.83) 3981.83,4510.17 C81.2@4037.48,4510.17 ; v1(3981.17,4556.83) 3981.88,4556.12 C82.2@4037.73,4556.12 ; v1(3981.17,4605.83) 3981.76,4605.24 C83.2@4038.01,4605.24 ; v1(3981.23,2278.72) 3981.88,2278.07 C102.2@4037.54,2278.07 ; v1(3981.23,2324.72) 3981.94,2324.01 C103.2@4037.79,2324.01 ; v1(3981.23,2373.72) 3981.81,2373.13 C104.2@4038.06,2373.13 ; v1(3982.5,5103.5) 3982.84,5103.16 4041.02,5103.16 C71.2@4041.37,5102.82 ; v1(3983,5151) 3983.16,5151.16 4041.21,5151.16 C72.2@4041.37,5151.32 ; v1(3983.07,2871.15) 3983.41,2870.81 C99.2@4041.59,2870.81 ; v1(3983.5,5054) 3983.75,5054.25 4041.63,5054.25 C70.2@4041.88,5054.5 ; v1(3983.57,2918.65) 3983.73,2918.81 C100.2@4041.78,2918.81 ; v1(3983.57,3532.15) 3983.91,3531.81 C91.2@4042.09,3531.81 ; v1(3984,4912.5) 3984.65,4911.85 4040.31,4911.85 C67.2@4040.96,4911.19 ; v1(3984,4958.5) 3984.71,4957.79 4040.56,4957.79 C68.2@4041.27,4957.08 ; v1(3984,5007.5) 3984.59,5006.91 4040.83,5006.91 C69.2@4041.42,5006.33 ; v1(3984.07,2821.65) 3984.32,2821.9 C98.2@4042.2,2821.9 ; v1(3984.07,3579.65) 3984.23,3579.81 C92.2@4042.28,3579.81 ; v1(3984.57,2680.15) 3985.22,2679.5 C95.2@4040.88,2679.5 ; v1(3984.57,2726.15) 3985.28,2725.44 C96.2@4041.13,2725.44 ; v1(3984.57,2775.15) 3985.16,2774.57 C97.2@4041.4,2774.57 ; v1(3984.57,3482.65) 3984.82,3482.9 C90.2@4042.7,3482.9 ; v1(3985.07,3341.15) 3985.72,3340.5 C87.2@4041.38,3340.5 ; v1(3985.07,3387.15) 3985.78,3386.44 C88.2@4041.63,3386.44 ; v1(3985.07,3436.15) 3985.66,3435.57 C89.2@4041.9,3435.57 ; v1(4281,3990.91) 4300.35,3971.57 U26.22@4332.86,3971.57 ; v1(4285,2523.91) 4304.35,2504.57 U30.22@4336.86,2504.57 ; v1(4285,2925.41) 4304.35,2906.07 U29.22@4336.86,2906.07 ; v1(4285,3583.91) 4304.35,3564.57 U28.22@4336.86,3564.57 ; v1(4285,4750) 4304.35,4730.65 U27.22@4336.86,4730.65 ; U26.13@4332.86,3741.25 4334.5,3739.61 v1(4334.5,3710.5) ; U30.13@4336.86,2274.25 4337.5,2273.61 v1(4337.5,2246) ; U29.13@4336.86,2675.75 4337.5,2675.11 v1(4337.5,2647.5) ; U28.13@4336.86,3334.25 4336.86,3307.14 v1(4337.5,3306.5) ; U27.13@4336.86,4500.34 4337.5,4499.7 v1(4337.5,4469.5) ; U25.13@4336.86,4906.25 4338.5,4904.61 v1(4338.5,4876) ; C154.2@4381.3,3005.08 4381.37,3005.15 4519.99,3005.15 C101.1@4520.06,3005.21 ; C120.2@4381.62,4073 4382.62,4074 v1(4449.5,4074) 4521.88,4074 C80.1@4522.88,4075 ; C132.2@4384.14,3665.11 4384.34,3665.31 4521.18,3665.31 C94.1@4521.38,3665.5 ; C126.2@4384.68,4829.5 4385.02,4829.85 4522.19,4829.85 C93.1@4522.53,4830.19 ; C162.2@4387.12,2603 4387.18,2603.05 4522.41,2603.05 C108.1@4522.46,2603.11 ; U26.12@4565.14,3741.25 4565.51,3741.25 4569.07,3737.69 v1(4569.07,3710.38) ; U26.10@4565.14,3792.43 U26.9@4565.14,3817.81 ; U26.9@4565.14,3818.02 U26.9@4565.14,3817.81 ; v1(4567,3307) 4567,3332.11 U28.12@4569.14,3334.25 ; v1(4567.5,4472) 4567.5,4498.7 U27.12@4569.14,4500.34 ; v1(4569,2246) 4569,2274.11 U30.12@4569.14,2274.25 ; v1(4569,2647) 4569,2675.61 U29.12@4569.14,2675.75 ; U30.10@4569.14,2325.43 U30.9@4569.14,2351.02 v1(4619,2351.01) ; U29.10@4569.14,2726.93 U29.9@4569.14,2752.52 v1(4619,2752.5) ; U28.10@4569.14,3385.43 4569.14,3407.46 4572.68,3411 4575.16,3411 v1(4619,3411) ; U27.10@4569.14,4551.52 U27.9@4569.14,4577.11 4569.95,4576.31 4614.19,4576.31 v1(4615,4575.5) ; U25.12@4569.14,4906.25 4569.5,4905.89 v1(4569.5,4874.5) ; U25.10@4569.14,4957.43 U25.9@4569.14,4983.02 4607.36,4983.02 4614.88,4975.5 v1(4617.5,4975.5) ; v1(4611.5,3818.5) 4611.26,3818.26 4565.6,3818.26 U26.9@4565.14,3817.81 ; R132.2@4682.12,3766.5 4682.62,3766 4721.5,3766 v1(4722,3765.5) ; R159.2@4684.62,4528.5 4684.87,4528.75 4723.75,4528.75 v1(4724,4529) ; R200.2@4686.62,2300 4687.62,2299 4728,2299 v1(4729,2298) ; R186.2@4689.12,2702 4689.62,2701.5 4729,2701.5 v1(4729.5,2701) ; R160.2@4690.62,3360 4690.87,3360.25 4730.25,3360.25 v1(4730.5,3360.5) ; R131.2@4697.12,4930.5 4699.5,4928.12 v1(4699.5,4894.5) ; v1(5317,6993) C175.2@5317,7031.38 ; v1(5467,6993) C176.2@5467,7031.38 ; v1(5617,6994) C179.2@5617,7033.38 ; v1(5768,6992) C182.2@5768,7031.38 ; v1(7716,3502) 7716.5,3501.5 7749.81,3501.5 C45.2@7750.31,3501 ; v1(7841,3813) 7841.5,3813.5 7878.82,3813.5 R83.1@7879.32,3814 ; R84.1@8021.68,4550 8021.68,4524.31 8031,4515 8047,4515 v1(8048,4514)
  L08 - BOTTOM w15: v1(4288.5,5152.5) 4289.77,5152.5 4305.18,5137.09 4336.34,5137.09 U25.22@4336.86,5136.57 ; C112.2@4387.12,5235 4388.62,5236.5 v1(4462,5236.5) 4521.38,5236.5 C79.1@4522.88,5238
  L08 - BOTTOM w50: v1(6106.5,7112.5) 6106,7113 R252.1@6106,7535.45 6127.65,7535.45 6135.47,7543.26 6242.5,7543.26 C150.2@6249,7549.76
  other v1: 1536.5,696.5 1566.5,696.5 1594.5,696.5 4333,696.5 1622.5,697 4361,697 4389,697 4419,697 1653.5,697.5 1683.5,697.5 1711.5,697.5 1739.5,698 4450,697.5 4478,698 4506,698 4536,698 6786,796 6807,796 5939.97,799.73 6024.65,799.73 6066.98,799.73 6807,816 6786,817 6139,818 6165,818 6189,818 5874,819 5910,819 6097,819 6786,837 5939.97,839.1 6024.65,839.1 6066.98,839.1 6554,1160 6583,1160 6610,1160 6637,1160 4458.5,1361.5 6101,1377 6121,1408 6146,1408 6171,1408 6195,1408 5536,1428 5562,1428 5589,1428 4458,1450.5 5627,1456 8000.5,1463 5627,1478 8000.5,1493 8000.5,1521 8000,1549 7999.5,1580 7999.5,1610 7999.5,1638 4459.16,1666 7999,1666 4457.5,1753.5 4458.5,2060.5 6322,2552 4459.16,2603.5 4458.5,3006 4459.16,3033 4455.5,3120.5 5933.07,3580.31 6267.72,3580.31 6468.5,3580.31 5733.49,3581.51 5535.09,3583.91 5598.43,3647.24 5799.21,3647.24 6000,3647.24 6200.79,3647.24 6401.57,3647.24 6602.36,3647.24 4459.16,3666 5864.97,3713 5665.35,3714.17 6066.93,3714.17 6133.86,3714.17 6334.41,3714.41 6535.6,3714 5330.71,3781.1 5732.28,3781.1 5933.07,3781.1 6267.41,3781.41 6468.5,3781.1 6669.29,3781.1 5397.64,3848.03 5799.04,3847.85 6602.36,3848.03 5665.5,3915.1 6535.43,3914.95 5732.28,3981.88 6468.5,3981.88 6669.29,3981.88 1543,4025 1573,4025 1601,4025 1629,4025.5 1660,4026 1690,4026 1718,4026 1746,4026.5 6602.36,4048.81 4459.16,4110 6535.43,4115.74 6671,4180.96 5334.66,4186.67 4457.5,4194.5 6635.83,4249.6 5332.58,4314.66 6671,4318.24 6535.43,4383.46 5599.41,4449.41 6602.36,4450.39 5531.5,4517.32 6468.5,4517.32 5730.29,4519.31 6671,4519.03 5464.57,4584.25 6535.43,4584.25 5799.21,4651.17 6602.36,4651.17 5594.5,4656 5732.28,4718.1 5933.07,4718.1 6267.72,4718.1 6469.2,4718.8 6671,4719.81 5464.57,4785.03 5866.14,4785.03 6066.93,4785.03 6335.06,4785.44 6535.43,4785.03 4455.5,4830.5 5799.21,4851.96 6000,4851.96 6401.57,4851.96 6602.36,4851.96 5934.23,4917.73 5531.5,4918.89 5732.28,4918.89 6468.5,4918.89 7731.5,4925.5 7761.5,4925.5 7789.5,4925.5 7817.5,4926 7848.5,4926.5 7878.5,4926.5 7906.5,4926.5 7934.5,4927 4453.5,5290.5 4458.67,5480.66 4459.16,5831 4459.16,5927.5 4459.16,6258 6659.13,6432.03 6703.03,6432.03 6756.97,6432.03 5534.28,6432.5 5578.17,6432.5 5632.11,6432.5 8028.5,6458 5578.17,6486.44 5632.11,6486.44 6703.03,6485.97 6756.97,6485.97 8028.5,6488 8028.5,6516 8028,6544 8027.5,6575 8027.5,6605 8027.5,6633 8027,6661 6257.04,6983.7 6119,7139 6092,7139.5 4821,7255 1524,7269.5 1554,7269.5 1582,7269.5 1610,7270 1641,7270.5 1671,7270.5 1699,7270.5 1727,7271 4821,7285 4821,7313 4820.5,7341 4820,7372 4820,7402 4820,7430 4819.5,7458
GND_USB: C34.2 C36.2 C37.2 C38.2 C39.2 C40.2 D6.2 D7.2 D8.1 D9.1 J2.5 J2.Z1 J2.Z2 J2.Z3 J2.Z4 J3.1 U12.4 U12.17 U12.20 U12.24 U12.26 U12.33 U13.5 U14.2 U14.5 | length 994.1
  L01 - TOP w6: v1(7776,5073) C37.2@7776,5108.31 ; D6.2@7806,5212.7 7806.25,5212.45 7806.25,5187.39 v1(7806.5,5187.14)
  L01 - TOP w8: U13.5@6979.27,5343 v1(7063,5343) ; C34.2@7047,5535.69 v1(7047,5571) ; v1(7489,5842) C39.2@7533.31,5842 ; v1(7495.5,5109) 7495.6,5109.1 7525.86,5109.1 D8.1@7525.95,5109.2 ; U14.5@7633.06,5843.2 7636.41,5843.2 7649.2,5856 U14.2@7654.13,5856 7654.63,5856.5 7687.5,5856.5 v1(7688,5857) 7716,5857 7730.69,5842.31 C40.2@7730.69,5822 ; D9.1@7698.65,5935 v1(7736,5935) ; v1(7709,5036) 7709,5077.47 C38.2@7710,5078.47 ; v1(7773.5,5310) 7773.75,5309.75 7773.75,5284.05 D7.2@7774,5283.8 ; v1(7824,5314) 7824.91,5313.09 7877.09,5313.09 J2.5@7878,5312.18
  L08 - BOTTOM w6: v1(7445,5239.5) 7445.06,5239.56 U12.26@7480.93,5239.63 U12.26@7480.93,5239.63
  L08 - BOTTOM w8: v1(7429,5400) 7429.16,5400.16 7429.16,5428.84 C36.2@7429.31,5429 ; U12.24@7503.57,5197.31 7503.57,5171.43 7509,5166 7525,5166 v1(7526.55,5164.45) 7569.45,5164.45 7582.31,5177.31 U12.20@7582.31,5197.31 7582.31,5279 U12.33@7572.46,5288.84 7562.62,5298.69 U12.4@7562.62,5380.38 U12.4@7560.72,5382.28 ; v1(7617,5242) 7619.31,5242 7641.36,5219.94 U12.17@7641.36,5197.31
  other v1: 7523,5339
GPIO0_15: U7.1 U44.6 | length 6012.3
  L01 - TOP w8: U44.6@4571.33,6008.19 4620.81,6008.19 v1(4621,6008)
  L03 - SIG w6: v1(4621,6008) 4652,6008 4681,5979 4681,5586.3 4518.5,5423.8 4518.5,2779.44 4673.94,2624 4873.5,2624 5019.5,2770 6838.51,2770 6897,2711.51 v1(6897,2675)
  L08 - BOTTOM w6: v1(6897,2675) 6916,2675 6923.38,2667.62 U7.1@6923.38,2637.53
GPIO0_16: U7.4 U46.1 | length 6694.1
  L01 - TOP w8: U46.1@4497.29,6564.41 4531.93,6564.41 4541.34,6555 v1(4544.5,6555)
  L03 - SIG w6: v1(4544.5,6555) 4621.5,6555 4694,6482.5 4694,5574.61 4536.61,5417.23 4536.61,2787.58 4682.19,2642 4858,2642 5006,2790 6536.5,2790 6537.24,2790.74 6915.65,2790.74 6995,2711.39 v1(6995,2675)
  L08 - BOTTOM w6: U7.4@6970.62,2639.5 6970.62,2664.62 6980,2674 6994,2674 v1(6995,2675)
GPIO0_17: U7.8 U45.7 | length 3122.9
  L01 - TOP w8: U45.7@4568.15,2170.49 v1(4618.5,2170.5)
  L03 - SIG w6: v1(4618.5,2170.5) 7086,2170.5 7206,2290.5 7206,2448 7088,2566 v1(7028,2566)
  L08 - BOTTOM w6: U7.8@6994.24,2584.38 7024.62,2584.38 7029,2580 7029,2567 v1(7028,2566)
GPIO0_30: U10.11 U42.7 | length 4815.4
  L01 - TOP w8: U42.7@4569.15,6372.49 v1(4619.5,6372.5)
  L03 - SIG w6: v1(4619.5,6372.5) 4579.4,6372.5 4533.59,6326.69 4533.59,5819.69 4495.45,5781.55 4495.45,2777.05 4671,2601.5 4834.38,2601.5 4925.37,2510.51 5399.51,2510.51 v1(5433,2544)
  L08 - BOTTOM w6: U10.11@5432.13,2576.5 5432.56,2576.07 5432.56,2544.44 v1(5433,2544)
GPIO0_31: MD1.AB11 U44.7 | length 3716.4
  L01 - TOP w6: v1(4849,5310) 4849.19,5309.81 4849.19,4243.31 5092.98,3999.52 5092.98,3611.52 5236,3468.5 5948.5,3468.5 5966.54,3486.54 MD1.AB11@5966.54,3546.84
  L01 - TOP w8: U44.7@4571.15,6033.99 v1(4621.5,6034)
  L08 - BOTTOM w6: v1(4621.5,6034) 4700.83,6034 4850.5,5884.33 4850.5,5311.5 v1(4849,5310)
GPIO0_32: MD1.Y11 U44.5 | length 4667.4
  L01 - TOP w6: v1(5931,3712) 5933.12,3712 5964.42,3680.7 MD1.Y11@5966.54,3680.7
  L01 - TOP w8: U44.5@4571.24,5982.9 4620.9,5982.9 v1(4621,5983)
  L03 - SIG w6: v1(4931.5,3102) 5633,3102 5914.5,3383.5 5914.5,3695.5 v1(5931,3712)
  L08 - BOTTOM w6: v1(4621,5983) 4677,5983 4704.5,5955.5 4704.5,5331.44 4822.79,5213.15 4847.35,5213.15 4956.34,5104.16 4956.34,4272.84 4863,4179.5 4863,3967.44 4931.5,3898.94 v1(4931.5,3102)
GPIO0_41: MD1.AB12 U42.6 | length 4207.1
  L01 - TOP w6: v1(4831.34,5252) 4831,5251.66 4831,4225.95 5071.98,3984.98 5071.98,3595.52 5217.5,3450 6014,3450 6033.46,3469.46 MD1.AB12@6033.46,3546.84
  L01 - TOP w8: U42.6@4569.14,6346.89 4569.33,6346.69 4618.81,6346.69 v1(4619,6346.5)
  L08 - BOTTOM w6: v1(4619,6346.5) 4619.5,6347 4704.5,6347 4879.5,6172 4879.5,5265.5 4866,5252 v1(4831.34,5252)
GPIO0_42: MD1.AA12 U43.7 | length 3204.5
  L01 - TOP w6: v1(4617.5,1563.5) 4756,1563.5 4934.5,1742 v1(4934.5,2978) ; MD1.AA12@6033.46,3613.77 6033.6,3613.77 6066.37,3581 v1(6066.5,3581)
  L01 - TOP w8: U43.7@4569.14,1563.98 4569.38,1563.74 4617.26,1563.74 v1(4617.5,1563.5)
  L03 - SIG w6: v1(4934.5,2978) 5635.22,2978 6066.5,3409.28 v1(6066.5,3581)
GPIO0_43: MD1.W12 U42.5 | length 5415
  L01 - TOP w6: MD1.W12@6033.46,3747.63 6035.3,3747.63 6067.17,3779.5 v1(6069,3779.5)
  L01 - TOP w8: U42.5@4569.14,6321.3 4569.24,6321.4 4618.9,6321.4 v1(4619,6321.5)
  L03 - SIG w6: v1(4934,3007.5) 5633,3007.5 6035.36,3409.86 6035.36,3745.86 v1(6069,3779.5)
  L08 - BOTTOM w6: v1(4619,6321.5) 4620,6322.5 4712,6322.5 4868.34,6166.16 4868.34,5297.61 4852.49,5281.76 4827.26,5281.76 4813.5,5268 4813.5,5238 4827.35,5224.15 4851.91,5224.15 4967.34,5108.71 4967.34,4268.29 4875,4175.94 4875,3971 4950,3896 4950,3023.5 v1(4934,3007.5)
GPIO0_44: MD1.W11 U43.6 | length 3420
  L01 - TOP w6: v1(4617.5,1538) 4755,1538 4953.5,1736.5 4953.5,3050.66 v1(4932.16,3072) ; MD1.W11@5966.54,3747.63 5968.33,3747.63 5999.2,3778.5 v1(6001,3778.5)
  L01 - TOP w8: U43.6@4569.14,1538.39 4569.33,1538.19 4617.31,1538.19 v1(4617.5,1538)
  L03 - SIG w6: v1(4932.16,3072) 5636.2,3072 5979,3414.8 5979,3756.5 v1(6001,3778.5)
GPMC_AD0: MD1.Y10 U7.2 | length 1817.2
  L01 - TOP w6: v1(5866,3646.93) 5866,3647.01 5899.61,3680.62 MD1.Y10@5899.61,3680.7
  L08 - BOTTOM w6: v1(5866,3646.93) 5866.07,3647 5894,3647 5979,3562 5979,3356 6355,2980 6869,2980 6934.38,2914.62 6934.38,2835.47 6934.38,2708.43 6934.38,2669.39 6939.13,2664.64 U7.2@6939.13,2639.5
GPMC_AD1: MD1.AA10 U7.5 | length 2078.1
  L01 - TOP w6: v1(5867,3577) 5867,3579.08 5899.61,3611.69 MD1.AA10@5899.61,3613.77
  L08 - BOTTOM w6: v1(5867,3577) 5837,3607 5837,3648 5853.77,3664.77 5907.23,3664.77 5996,3576 5996,3354.56 6347.56,3003 6937,3003 7027,2913 7027,2645 7013.62,2631.62 U7.5@6994.24,2631.62
GPMC_AD2: MD1.W9 U7.7 | length 2133.2
  L01 - TOP w6: v1(5802,3713) 5802,3714.98 5832.68,3745.65 MD1.W9@5832.68,3747.63
  L08 - BOTTOM w6: v1(5802,3713) 5839.23,3675.77 5917.23,3675.77 6014,3579 6014,3352.11 6345.11,3021 6945,3021 7056,2910 7056,2816 7056,2653 7056,2612 7042.16,2598.16 7019.61,2598.16 7017.64,2600.13 U7.7@6994.24,2600.13
GPMC_AD3: MD1.AA9 U7.10 | length 2080
  L01 - TOP w6: v1(5800,3579) 5800,3580.05 5832.68,3612.73 MD1.AA9@5832.68,3613.77 ; v1(6857,2687) 6883.77,2687 6889.61,2692.84 6961.39,2692.84 6971.84,2682.39 6971.84,2539.55 6964,2531.7 v1(6964,2528)
  L08 - BOTTOM w6: v1@5800,3575.97 v1(5800,3579) 5820,3559 5902,3559 5927,3534 5927,3295 6270,2952 6684,2952 6781,2952 6815,2952 6857,2910 v1(6857,2687) ; U7.10@6954.87,2576.5 6955,2576.38 6955,2561 6958.84,2557.16 6958.84,2544.31 6961.38,2541.77 6961.38,2530.62 v1(6964,2528)
GPMC_AD4: MD1.AB9 U8.2 | length 1260.5
  L01 - TOP w6: MD1.AB9@5832.68,3546.84 5832.84,3546.68 5832.84,3510.16 v1(5833,3510)
  L08 - BOTTOM w6: v1(5833,3510) 5833,3507.42 5833,3306.53 5833,3303 6240,2896 6414,2896 6434.38,2875.62 6434.38,2840.67 6434.38,2684.01 6434.38,2668.39 6439.13,2663.64 U8.2@6439.13,2639.5
GPMC_AD5: MD1.W8 U8.5 | length 1726.3
  L01 - TOP w6: v1(5733,3713) 5733,3713.94 5765.75,3746.69 MD1.W8@5765.75,3747.63
  L08 - BOTTOM w6: v1(5733,3713) 5719.68,3699.68 5719.19,3699.68 5712,3692.49 5712,3575 5757,3530 5882,3530 5896,3516 5896,3282 6265,2913 6496,2913 6545,2864 6545,2660 6516.62,2631.62 U8.5@6494.24,2631.62
GPMC_AD6: MD1.Y8 U8.7 | length 1688.1
  L01 - TOP w6: v1(5735,3646) 5735,3647.98 5765.75,3678.73 MD1.Y8@5765.75,3680.7
  L08 - BOTTOM w6: v1(5735,3646) 5735,3610 5799,3546 5893,3546 5912,3527 5912,3289 6274,2927 6508,2927 6562,2873 6562,2616 6544.16,2598.16 6520.71,2598.16 6518.74,2600.13 U8.7@6494.24,2600.13
GPMC_AD7: MD1.AB8 U8.10 | length 1438.5
  L01 - TOP w6: MD1.AB8@5765.75,3546.84 5765.87,3546.72 5765.87,3510.13 v1(5766,3510) ; v1(6367,2686) 6390.77,2686 6395.61,2690.84 6462.39,2690.84 6472.84,2680.39 6472.84,2536.55 6464,2527.7 v1(6464,2524)
  L08 - BOTTOM w6: v1@5765.94,3510.06 v1(5766,3510) 5766,3324 6367,2723 v1(6367,2686) ; U8.10@6454.87,2576.5 6454.87,2556.58 6459.06,2552.39 6459.06,2532.64 6464,2527.7 v1(6464,2524)
GPMC_AD8: MD1.Y7 U9.2 | length 1184.5
  L01 - TOP w6: v1(5668,3648) 5668,3648.94 5698.82,3679.76 MD1.Y7@5698.82,3680.7
  L08 - BOTTOM w6: v1(5668,3648) 5643,3623 5643,3557 5674,3526 5674,3158 5928.38,2903.62 5928.38,2671.39 5933.13,2666.64 U9.2@5933.13,2639.5
GPMC_AD9: MD1.AA7 U9.5 | length 1178.6
  L01 - TOP w6: v1(5667,3576) 5667,3578.98 5698.82,3610.8 MD1.AA7@5698.82,3613.77
  L08 - BOTTOM w6: v1(5667,3576) 5696,3547 5696,3197 6033,2860 6033,2654 6021,2642 6019.43,2642 6009.06,2631.62 U9.5@5988.24,2631.62
GPMC_AD10: MD1.W6 U9.7 | length 1428.8
  L01 - TOP w6: v1(5600,3714) 5600,3714.87 5631.89,3746.76 MD1.W6@5631.89,3747.63
  L08 - BOTTOM w6: v1(5600,3714) 5600.17,3714.17 5633.83,3714.17 5692,3656 5692,3576.19 5708.84,3559.35 5708.84,3212.16 6059,2862 6059,2622 6037.13,2600.13 U9.7@5988.24,2600.13
GPMC_AD11: MD1.AA6 U9.10 | length 1375.9
  L01 - TOP w6: v1(5598,3578) 5598,3578.94 5631.89,3612.83 MD1.AA6@5631.89,3613.77 ; v1(5857,2689) 5881.77,2689 5886.61,2693.84 5956.39,2693.84 5966.84,2683.39 5966.84,2540.57 5953.89,2527.62 v1(5953.89,2526.87)
  L08 - BOTTOM w6: v1(5598,3578) 5654,3522 5654,3126 5857,2923 v1(5857,2689) ; U9.10@5948.87,2576.5 5948.87,2557.36 5953.62,2552.61 5953.62,2527.14 v1(5953.89,2526.87)
GPMC_AD12: MD1.AB6 U10.2 | length 992.7
  L01 - TOP w6: v1(5598,3510) 5598,3511.48 5631.89,3545.37 MD1.AB6@5631.89,3546.84
  L08 - BOTTOM w6: U10.2@5432.13,2639.5 5432.13,2660.31 5429,2663.43 5429,2887 5598,3056 v1(5598,3510)
GPMC_AD13: MD1.W5 U10.5 | length 1288.2
  L01 - TOP w8: v1(5532.72,3714.28) 5532.72,3714.84 5564.96,3747.08 MD1.W5@5564.96,3747.63
  L08 - BOTTOM w6: U10.5@5487.24,2631.62 5508.06,2631.62 5621,2744.57 5621,3518 5597.98,3541.02 5596,3543 5539,3543 5508,3574 5508,3691 5531.28,3714.28 v1(5532.72,3714.28)
GPMC_AD14: MD1.Y5 U10.7 | length 1229.2
  L01 - TOP w8: v1(5533,3645) 5533,3646.87 5564.96,3678.83 MD1.Y5@5564.96,3680.7
  L08 - BOTTOM w6: U10.7@5487.24,2600.13 5527.39,2600.13 5637,2709.74 5637,3522 5602,3557 5590.5,3557 5533,3614.5 v1(5533,3645)
GPMC_AD15: MD1.AB5 U10.10 | length 1294.6
  L01 - TOP w6: v1(5363,2676) 5364.13,2676 5386.97,2698.84 5454.39,2698.84 5465.84,2687.39 5465.84,2536.55 5458,2528.7 v1(5458,2525) ; v1(5529,3511) 5529.06,3511 5564.9,3546.84 MD1.AB5@5564.96,3546.84
  L08 - BOTTOM w6: v1(5363,2676) 5361,2678 5361,2859.5 5529,3027.5 v1(5529,3511) ; U10.10@5447.87,2576.5 5447.87,2555.69 5452,2551.57 5452,2540 5455.38,2536.62 5455.38,2527.62 v1(5458,2525)
JTAG_cTI_RTCK: J6.9
JTAG_cTI_TCK: J6.11 R92.2 | length 128.8
  L01 - TOP w5: R92.2@7608.69,4349 J6.11@7737.5,4349
JTAG_EMU0: J6.13 MD1.K18 R86.1 | length 1598.7
  L01 - TOP w6: MD1.K18@6435.04,4349.99 6436.52,4349.99 6467.52,4381 v1(6469,4381) ; v1(7244,4512) 7244,4440 7465,4219 7585,4219 7609,4243 7609,4298.31 R86.1@7609.68,4299 J6.13@7737.5,4299
  L08 - BOTTOM w6: v1(6469,4381) 6580.5,4492.5 7224.5,4492.5 v1(7244,4512)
